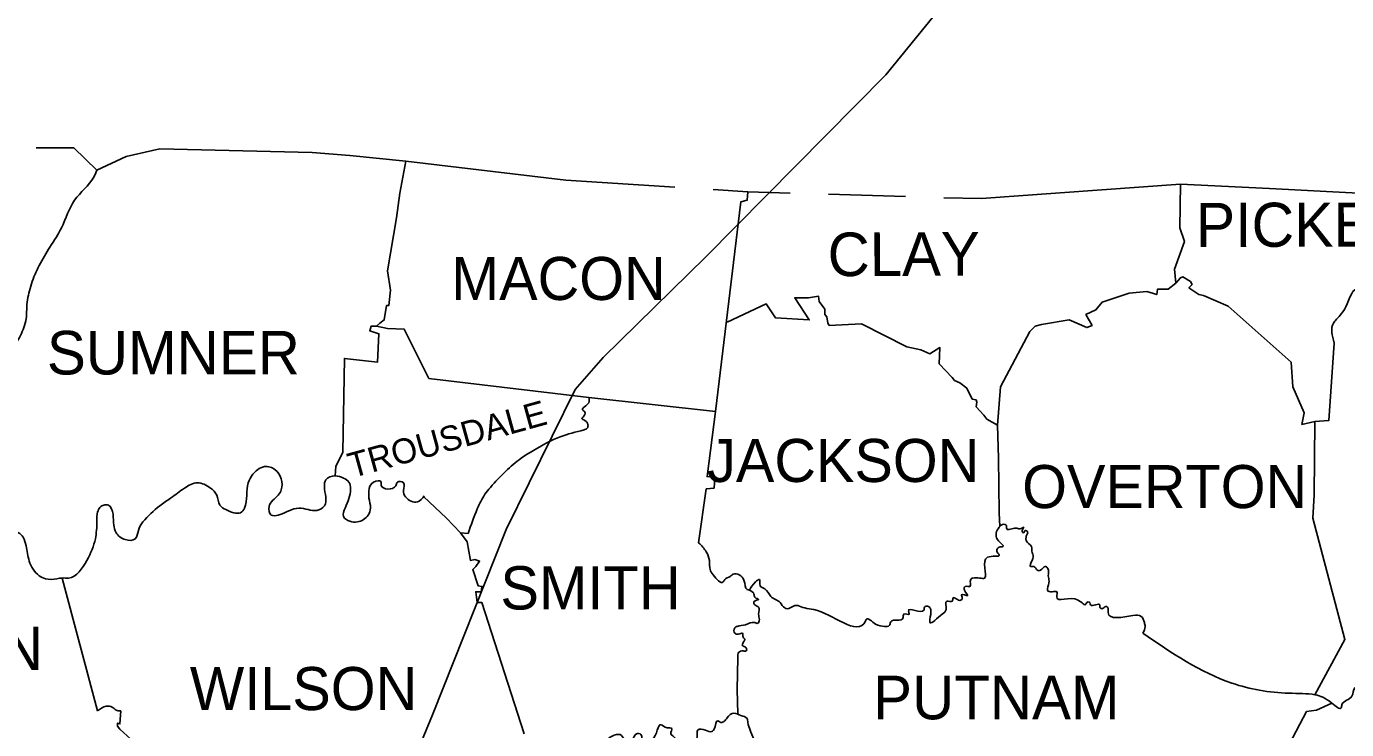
# Model space of a CAD drawing. Extents: x 1577619 to 1828281, y 483481 to 598136.
# Drawn here: x 1703569 to 1707004, y 532387 to 534218 of the extents above; entities that cross this region are included whole.
import ezdxf

# ---------------------------------------------------------------- set-up
doc = ezdxf.new("R2010")
doc.units = 0
for name, color, linetype in [('DESIGN - SHEET - Corner Text', 7, 'Continuous'), ('DESIGN - SHEET - Linework', 7, 'Continuous'), ('SURVEY - CENTERLINE - Preliminary Text', 7, 'Continuous')]:
    doc.layers.add(name, color=color, linetype=linetype)

msp = doc.modelspace()

# ---------------------------------------------------------------- linework, layer by layer
at = {"layer": 'DESIGN - SHEET - Linework'}
msp.add_line((1705656.2, 533781.6), (1705856.2, 533775.6), dxfattribs=at)
for points in [[(1703594.2, 533901.6), (1703692.2, 533901.6), (1703752.2, 533843.6), (1703828.2, 533879.6), (1703916.2, 533899.6), (1704312.2, 533889.6), (1704410.2, 533881.6)], [(1704410.2, 533881.6), (1704556.2, 533867.6), (1704972.2, 533817.6), (1705256.2, 533799.6)], [(1704480.2, 533437.6), (1704488.2, 533445.6), (1704500.2, 533453.6), (1704506.2, 533491.6), (1704512.2, 533491.6), (1704516.2, 533531.6), (1704508.2, 533581.6), (1704532.2, 533719.6), (1704540.2, 533783.6), (1704556.2, 533867.6)], [(1705956.2, 533771.6), (1706054.2, 533769.6), (1706572.2, 533807.6), (1706804.2, 533795.6)], [(1706572.2, 533807.6), (1706570.2, 533693.6), (1706582.2, 533657.6), (1706556.2, 533585.6), (1706560.2, 533549.6)], [(1706804.2, 533795.6), (1707646.2, 533751.6), (1707652.2, 533751.6)], [(1705318.2, 532873.6), (1705338.2, 533013.6), (1705358.2, 533015.6), (1705360.2, 533043.6), (1705340.2, 533045.6), (1705362.2, 533215.6), (1705428.2, 533761.6), (1705444.2, 533765.6), (1705446.2, 533787.6)], [(1705356.2, 533793.6), (1705446.2, 533787.6), (1705556.2, 533783.6)], [(1706972.2, 533393.6), (1706958.2, 533191.6), (1706922.2, 533189.6), (1706888.2, 533181.6), (1706894.2, 533211.6), (1706864.2, 533279.6), (1706860.2, 533343.6), (1706696.2, 533489.6), (1706632.2, 533517.6), (1706620.2, 533519.6), (1706594.2, 533537.6), (1706602.2, 533545.6), (1706598.2, 533553.6), (1706578.2, 533565.6), (1706572.2, 533563.6), (1706560.2, 533549.6), (1706540.2, 533533.6), (1706512.2, 533533.6), (1706510.2, 533519.6), (1706484.2, 533527.6), (1706438.2, 533523.6), (1706368.2, 533499.6), (1706352.2, 533479.6), (1706326.2, 533467.6), (1706342.2, 533439.6), (1706328.2, 533433.6), (1706282.2, 533453.6), (1706210.2, 533441.6), (1706194.2, 533437.6), (1706180.2, 533423.6), (1706104.2, 533279.6), (1706096.2, 533179.6), (1706098.2, 533093.6), (1706100.2, 532951.6), (1706102.2, 532915.6)], [(1705392.2, 533447.6), (1705494.2, 533495.6), (1705518.2, 533459.6), (1705606.2, 533453.6), (1705568.2, 533511.6), (1705604.2, 533511.6), (1705630.2, 533515.6), (1705632.2, 533501.6), (1705646.2, 533481.6), (1705646.2, 533467.6), (1705652.2, 533461.6), (1705654.2, 533445.6), (1705658.2, 533439.6), (1705742.2, 533443.6), (1705860.2, 533383.6), (1705896.2, 533375.6), (1705920.2, 533365.6), (1705946.2, 533381.6), (1705944.2, 533339.6), (1705978.2, 533303.6), (1705984.2, 533295.6), (1705998.2, 533289.6), (1706016.2, 533275.6), (1706030.2, 533247.6), (1706040.2, 533245.6), (1706042.2, 533239.6), (1706040.2, 533227.6), (1706060.2, 533205.6), (1706068.2, 533195.6), (1706096.2, 533179.6)], [(1704372.2, 533047.6), (1704374.2, 533071.6), (1704392.2, 533109.6), (1704396.2, 533353.6), (1704482.2, 533343.6), (1704486.2, 533417.6), (1704462.2, 533425.6), (1704466.2, 533437.6), (1704472.2, 533437.6), (1704480.2, 533437.6), (1704508.2, 533431.6), (1704552.2, 533429.6), (1704616.2, 533301.6), (1705032.2, 533251.6), (1705362.2, 533215.6)], [(1706922.2, 533189.6), (1706920.2, 532997.6), (1706916.2, 532937.6), (1707000.2, 532621.6), (1706922.2, 532477.6)], [(1704602.2, 532993.6), (1704662.2, 532937.6), (1704698.2, 532899.6), (1704716.2, 532875.6), (1704724.2, 532827.6), (1704736.2, 532829.6), (1704748.2, 532825.6), (1704738.2, 532811.6), (1704730.2, 532803.6), (1704744.2, 532761.6), (1704754.2, 532759.6), (1704752.2, 532745.6), (1704738.2, 532745.6), (1704742.2, 532717.6), (1704754.2, 532717.6), (1704864.2, 532375.6)], [(1704698.2, 532899.6), (1704718.2, 532897.6)], [(1703662.2, 532781.6), (1703754.2, 532435.6)], [(1705420.2, 532573.6), (1705418.2, 532491.6), (1705420.2, 532427.6)], [(1706966.2, 532455.6), (1706926.2, 532437.6), (1706900.2, 532433.6), (1706856.2, 532349.6)], [(1703814.2, 532435.6), (1703812.2, 532401.6), (1703806.2, 532403.6), (1703806.2, 532395.6), (1703812.2, 532387.6), (1703840.2, 532361.6)]]:
    msp.add_lwpolyline(points, dxfattribs=at)
for points in [[(1703108.2, 533105.6), (1703124.2, 533101.6), (1703144.2, 533083.6), (1703156.2, 533063.6), (1703174.2, 533071.6), (1703184.2, 533065.6), (1703202.2, 533075.6), (1703208.2, 533081.6), (1703232.2, 533085.6), (1703242.2, 533093.6), (1703248.2, 533107.6), (1703250.2, 533121.6), (1703242.2, 533125.6), (1703244.2, 533139.6), (1703256.2, 533143.6), (1703266.2, 533151.6), (1703270.2, 533161.6), (1703274.2, 533165.6), (1703296.2, 533177.6), (1703306.2, 533187.6), (1703314.2, 533205.6), (1703344.2, 533247.6), (1703356.2, 533249.6), (1703362.2, 533245.6), (1703372.2, 533245.6), (1703380.2, 533257.6), (1703386.2, 533257.6), (1703410.2, 533241.6), (1703450.2, 533235.6), (1703474.2, 533299.6), (1703506.2, 533345.6), (1703542.2, 533393.6), (1703562.2, 533433.6), (1703568.2, 533457.6), (1703570.2, 533493.6), (1703580.2, 533541.6), (1703588.2, 533565.6), (1703602.2, 533595.6), (1703630.2, 533643.6), (1703660.2, 533693.6), (1703694.2, 533765.6), (1703744.2, 533825.6), (1703752.2, 533843.6)], [(1707648.2, 533539.6), (1707634.2, 533553.6), (1707604.2, 533581.6), (1707562.2, 533609.6), (1707516.2, 533631.6), (1707462.2, 533657.6), (1707398.2, 533671.6), (1707346.2, 533679.6), (1707300.2, 533677.6), (1707230.2, 533667.6), (1707178.2, 533651.6), (1707166.2, 533659.6), (1707170.2, 533671.6), (1707162.2, 533677.6), (1707148.2, 533657.6), (1707126.2, 533653.6), (1707116.2, 533653.6), (1707116.2, 533635.6), (1707104.2, 533613.6), (1707084.2, 533601.6), (1707082.2, 533611.6), (1707070.2, 533613.6), (1707070.2, 533601.6), (1707074.2, 533569.6), (1707082.2, 533551.6), (1707070.2, 533559.6), (1707060.2, 533523.6), (1707038.2, 533533.6), (1707002.2, 533487.6), (1706978.2, 533455.6), (1706970.2, 533445.6), (1706972.2, 533393.6)], [(1705032.2, 533251.6), (1705032.2, 533237.6), (1705016.2, 533219.6), (1705022.2, 533213.6), (1705018.2, 533201.6), (1705014.2, 533197.6), (1705022.2, 533191.6), (1705030.2, 533181.6), (1705028.2, 533171.6), (1705020.2, 533167.6), (1704958.2, 533149.6), (1704888.2, 533113.6), (1704856.2, 533093.6), (1704816.2, 533059.6), (1704776.2, 533017.6), (1704762.2, 532999.6), (1704742.2, 532961.6), (1704718.2, 532897.6)], [(1703328.2, 533227.6), (1703334.2, 533219.6), (1703342.2, 533213.6), (1703342.2, 533199.6), (1703358.2, 533155.6), (1703366.2, 533113.6), (1703374.2, 533055.6), (1703390.2, 533053.6), (1703412.2, 533059.6), (1703468.2, 533053.6), (1703490.2, 533011.6), (1703486.2, 532997.6), (1703492.2, 532991.6), (1703500.2, 532969.6), (1703506.2, 532939.6), (1703520.2, 532909.6), (1703548.2, 532899.6), (1703560.2, 532887.6), (1703568.2, 532865.6), (1703576.2, 532825.6), (1703602.2, 532787.6), (1703618.2, 532779.6), (1703648.2, 532779.6), (1703662.2, 532781.6), (1703678.2, 532781.6), (1703726.2, 532827.6), (1703748.2, 532883.6), (1703752.2, 532929.6), (1703754.2, 532953.6), (1703760.2, 532965.6), (1703770.2, 532971.6), (1703782.2, 532971.6), (1703794.2, 532947.6), (1703796.2, 532919.6), (1703802.2, 532899.6), (1703826.2, 532881.6), (1703852.2, 532883.6), (1703860.2, 532905.6), (1703872.2, 532927.6), (1703916.2, 532969.6), (1703944.2, 532989.6), (1703980.2, 533015.6), (1704014.2, 533029.6), (1704048.2, 533015.6), (1704064.2, 532997.6), (1704072.2, 532971.6), (1704088.2, 532959.6), (1704108.2, 532951.6), (1704126.2, 532951.6), (1704136.2, 532963.6), (1704146.2, 533029.6), (1704158.2, 533051.6), (1704170.2, 533063.6), (1704188.2, 533071.6), (1704216.2, 533063.6), (1704232.2, 533011.6), (1704224.2, 532997.6), (1704200.2, 532967.6), (1704206.2, 532945.6), (1704224.2, 532945.6), (1704278.2, 532963.6), (1704302.2, 532959.6), (1704324.2, 532957.6), (1704344.2, 532969.6), (1704344.2, 533019.6), (1704348.2, 533037.6), (1704372.2, 533047.6), (1704394.2, 533041.6), (1704408.2, 533031.6), (1704412.2, 533013.6), (1704398.2, 532963.6), (1704394.2, 532941.6), (1704410.2, 532929.6), (1704430.2, 532927.6), (1704458.2, 532945.6), (1704464.2, 532963.6), (1704460.2, 532989.6), (1704460.2, 533007.6), (1704472.2, 533031.6), (1704492.2, 533031.6), (1704492.2, 533023.6), (1704530.2, 533021.6), (1704534.2, 533031.6), (1704550.2, 533029.6), (1704550.2, 533009.6), (1704570.2, 532981.6), (1704586.2, 532979.6), (1704604.2, 532995.6)], [(1705802.2, 532655.6), (1705814.2, 532657.6), (1705818.2, 532667.6), (1705850.2, 532677.6), (1705852.2, 532687.6), (1705866.2, 532687.6), (1705864.2, 532695.6), (1705904.2, 532697.6), (1705906.2, 532705.6), (1705916.2, 532707.6), (1705920.2, 532665.6), (1705952.2, 532687.6), (1705962.2, 532699.6), (1705964.2, 532721.6), (1705978.2, 532721.6), (1705980.2, 532729.6), (1706000.2, 532723.6), (1706004.2, 532729.6), (1706002.2, 532737.6), (1706018.2, 532735.6), (1706010.2, 532749.6), (1706012.2, 532759.6), (1706024.2, 532759.6), (1706026.2, 532777.6), (1706032.2, 532781.6), (1706062.2, 532781.6), (1706070.2, 532835.6), (1706100.2, 532841.6), (1706094.2, 532851.6), (1706100.2, 532861.6), (1706110.2, 532863.6), (1706096.2, 532881.6), (1706100.2, 532913.6), (1706112.2, 532921.6), (1706118.2, 532919.6), (1706120.2, 532909.6), (1706144.2, 532911.6), (1706154.2, 532909.6), (1706164.2, 532913.6), (1706160.2, 532901.6), (1706164.2, 532899.6), (1706168.2, 532905.6), (1706174.2, 532901.6), (1706172.2, 532893.6), (1706170.2, 532887.6), (1706170.2, 532879.6), (1706184.2, 532863.6), (1706186.2, 532847.6), (1706188.2, 532843.6), (1706186.2, 532827.6), (1706182.2, 532811.6), (1706190.2, 532811.6), (1706200.2, 532801.6), (1706208.2, 532801.6), (1706220.2, 532811.6), (1706226.2, 532807.6), (1706228.2, 532787.6), (1706230.2, 532773.6), (1706226.2, 532753.6), (1706226.2, 532749.6), (1706238.2, 532745.6), (1706250.2, 532745.6), (1706250.2, 532733.6), (1706306.2, 532723.6), (1706326.2, 532713.6), (1706328.2, 532717.6), (1706336.2, 532717.6), (1706338.2, 532711.6), (1706362.2, 532711.6), (1706362.2, 532705.6), (1706368.2, 532701.6), (1706378.2, 532707.6), (1706382.2, 532705.6), (1706384.2, 532691.6), (1706448.2, 532683.6), (1706470.2, 532681.6), (1706478.2, 532665.6), (1706480.2, 532655.6), (1706474.2, 532637.6)], [(1705318.2, 532873.6), (1705338.2, 532849.6), (1705346.2, 532827.6), (1705348.2, 532803.6), (1705356.2, 532789.6), (1705382.2, 532771.6), (1705386.2, 532777.6), (1705400.2, 532785.6), (1705408.2, 532791.6), (1705436.2, 532775.6), (1705444.2, 532751.6), (1705450.2, 532749.6), (1705462.2, 532739.6), (1705464.2, 532731.6), (1705474.2, 532725.6), (1705462.2, 532719.6), (1705464.2, 532711.6), (1705474.2, 532705.6), (1705474.2, 532687.6), (1705476.2, 532673.6), (1705472.2, 532663.6), (1705464.2, 532665.6), (1705440.2, 532659.6), (1705418.2, 532655.6), (1705412.2, 532651.6), (1705412.2, 532637.6), (1705422.2, 532635.6), (1705432.2, 532637.6), (1705434.2, 532627.6), (1705438.2, 532621.6), (1705434.2, 532613.6), (1705432.2, 532605.6), (1705442.2, 532599.6), (1705442.2, 532591.6), (1705434.2, 532591.6), (1705422.2, 532587.6), (1705420.2, 532573.6)], [(1705450.2, 532749.6), (1705466.2, 532771.6), (1705476.2, 532777.6), (1705478.2, 532761.6), (1705490.2, 532753.6), (1705506.2, 532733.6), (1705530.2, 532717.6), (1705542.2, 532703.6), (1705548.2, 532701.6), (1705568.2, 532709.6), (1705576.2, 532709.6), (1705594.2, 532703.6), (1705618.2, 532699.6), (1705752.2, 532669.6), (1705754.2, 532673.6), (1705778.2, 532661.6), (1705802.2, 532655.6)], [(1707410.2, 532543.6), (1707394.2, 532535.6), (1707384.2, 532531.6), (1707368.2, 532509.6), (1707354.2, 532507.6), (1707354.2, 532523.6), (1707304.2, 532525.6), (1707302.2, 532511.6), (1707284.2, 532535.6), (1707240.2, 532545.6), (1707210.2, 532547.6), (1707206.2, 532541.6), (1707174.2, 532541.6), (1707158.2, 532569.6), (1707144.2, 532567.6), (1707122.2, 532581.6), (1707116.2, 532575.6), (1707116.2, 532565.6), (1707098.2, 532547.6), (1707098.2, 532535.6), (1707078.2, 532535.6), (1707074.2, 532529.6), (1707060.2, 532521.6), (1707048.2, 532501.6), (1707026.2, 532495.6), (1707018.2, 532473.6), (1706992.2, 532451.6), (1706990.2, 532443.6), (1706966.2, 532455.6), (1706922.2, 532477.6), (1706854.2, 532481.6), (1706706.2, 532507.6), (1706474.2, 532637.6)], [(1703754.2, 532435.6), (1703776.2, 532447.6), (1703792.2, 532445.6), (1703802.2, 532437.6), (1703814.2, 532435.6)], [(1704876.2, 532331.6), (1704882.2, 532337.6), (1704892.2, 532337.6), (1704918.2, 532321.6), (1704938.2, 532321.6), (1704952.2, 532321.6), (1704964.2, 532321.6), (1704980.2, 532317.6), (1704992.2, 532331.6), (1705004.2, 532315.6), (1705012.2, 532315.6), (1705024.2, 532331.6), (1705034.2, 532323.6), (1705066.2, 532343.6), (1705104.2, 532373.6), (1705114.2, 532373.6), (1705126.2, 532361.6), (1705146.2, 532361.6), (1705156.2, 532375.6), (1705168.2, 532373.6), (1705172.2, 532357.6), (1705196.2, 532359.6), (1705220.2, 532399.6), (1705236.2, 532391.6), (1705248.2, 532389.6), (1705246.2, 532375.6), (1705256.2, 532365.6), (1705258.2, 532355.6), (1705286.2, 532349.6), (1705306.2, 532345.6), (1705314.2, 532369.6), (1705316.2, 532385.6), (1705336.2, 532385.6), (1705352.2, 532381.6), (1705358.2, 532387.6), (1705368.2, 532409.6), (1705376.2, 532405.6), (1705384.2, 532407.6), (1705392.2, 532417.6), (1705410.2, 532429.6), (1705428.2, 532423.6), (1705444.2, 532415.6), (1705446.2, 532405.6), (1705452.2, 532385.6), (1705462.2, 532361.6), (1705474.2, 532349.6), (1705490.2, 532353.6), (1705508.2, 532319.6), (1705502.2, 532295.6), (1705502.2, 532283.6), (1705496.2, 532279.6), (1705510.2, 532271.6), (1705514.2, 532263.6), (1705532.2, 532255.6), (1705548.2, 532275.6), (1705584.2, 532277.6), (1705598.2, 532277.6), (1705612.2, 532291.6), (1705630.2, 532281.6), (1705672.2, 532271.6), (1705680.2, 532275.6)]]:
    msp.add_spline(points, degree=3, dxfattribs=at)
at = {"layer": 'SURVEY - CENTERLINE - Preliminary Text'}
msp.add_lwpolyline([(1708884.7, 539906.9), (1708560.1, 539129.8), (1708111.1, 538112.8), (1707652, 537083.8), (1707394.3, 536547.6), (1707058.7, 536026.2), (1706600.7, 535283.6), (1706256.3, 534694.2), (1706126.1, 534487.2), (1705805.8, 534091.8), (1705336.8, 533617.7), (1705070, 533355.9), (1704997.1, 533272.5), (1704817.1, 532907.8), (1704625.9, 532425), (1704463.7, 532032), (1704343.5, 531826.9), (1704260.4, 531727.6), (1704089.3, 531621.1), (1703689.8, 531480.8), (1702865.5, 531262.5)], dxfattribs=at)

# ---------------------------------------------------------------- texts
at = {"layer": 'DESIGN - SHEET - Corner Text'}
for s, height, rotation, p in [('PICKETT', 114.82, 0.1429, (1706612.2, 533643.6)), ('CLAY', 113.36, 0.2558, (1705654.2, 533567.6)), ('TROUSDALE', 64.98, 15.4222, (1704416.2, 533041.6))]:
    msp.add_text(s, height=height, rotation=rotation, dxfattribs=at).set_placement(p)
for s, height, p in [('MACON', 112.16, (1704674.2, 533505.6)), ('SUMNER', 113.62, (1703622.2, 533311.6)), ('JACKSON', 112.16, (1705340.2, 533031.6)), ('OVERTON', 112.16, (1706160.2, 532963.6)), ('SMITH', 112.79, (1704802.2, 532699.6)), ('DAVIDSON', 113.36, (1702820.2, 532541.6)), ('WILSON', 112.16, (1703994.2, 532437.6)), ('PUTNAM', 113.62, (1705772.2, 532413.6))]:
    msp.add_text(s, height=height, dxfattribs=at).set_placement(p)

doc.saveas('drawing.dxf')
